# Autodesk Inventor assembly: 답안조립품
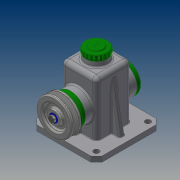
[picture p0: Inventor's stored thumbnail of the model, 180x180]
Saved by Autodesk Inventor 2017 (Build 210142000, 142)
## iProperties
Part Number: 답안조립품
Material: 일반
Document SubType Name: Assembly
Designer: 20
Author: 20
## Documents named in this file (14)
- C:\Users\20\Desktop\470818V1001\답안조립품.iam
- C:\Users\20\Desktop\470818V1001\본체.ipt
- C:\Users\20\Desktop\470818V1001\뒤커버.ipt
- C:\Users\20\Desktop\470818V1001\앞커버.ipt
- C:\Users\20\Desktop\470818V1001\베어링 15 x 35 x 11.ipt
- C:\Users\20\Desktop\470818V1001\축.ipt
- C:\Users\20\Desktop\470818V1001\오일실 15 25 7.ipt
- C:\Users\20\Desktop\470818V1001\볼트 M4 x 10.ipt
- C:\Users\20\Desktop\470818V1001\키 5 x 5 x 14.ipt
- C:\Users\20\Desktop\470818V1001\V-벨트풀리.ipt
- C:\Users\20\Desktop\470818V1001\와셔.ipt
- C:\Users\20\Desktop\470818V1001\볼트 M6 x 12.ipt
- C:\Users\20\Desktop\470818V1001\상부캡.ipt
- C:\Users\20\Desktop\470818V1001\멈춤링 15 x 1.ipt
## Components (1 placed, 1 different names)
1. V-벨트풀리:1 — 플러쉬:1
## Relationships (1: Flush 1)
- 플러쉬:1 [Flush]: V-벨트풀리:1
